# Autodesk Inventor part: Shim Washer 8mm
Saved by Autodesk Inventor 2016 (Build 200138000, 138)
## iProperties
Created: 2016-01
Part Number: Shim Washer 8mm
Material: Generic
Document SubType Name: Modeling
Designer: John
Density: 1 g/cm^3
Appearance: Default
Author: John
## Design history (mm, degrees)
feature "BOSS-EXTRUDE1"
body "Solid1"
